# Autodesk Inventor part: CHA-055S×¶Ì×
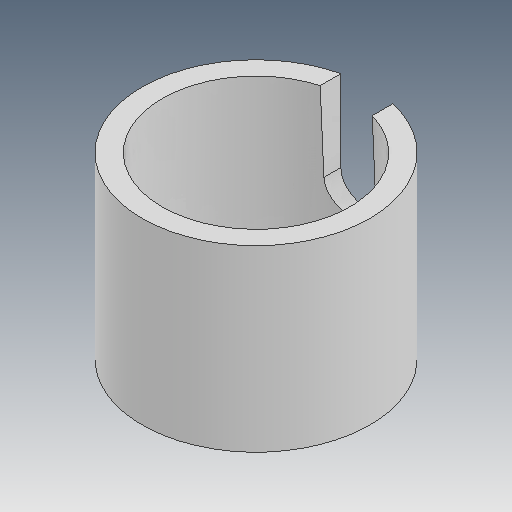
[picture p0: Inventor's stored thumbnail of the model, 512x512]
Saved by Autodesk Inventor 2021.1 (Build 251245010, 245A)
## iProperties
Created: 2019-12
Part Number: CHA-055S×¶Ì×
Material: Ogólny
Document SubType Name: Modeling
Designer: user
Density: 1 g/cm^3
Appearance: Domyślna
Author: user
Revision Number: ÈÎºÎ
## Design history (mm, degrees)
feature "ÊäÈë1"
node "Bryła1"
